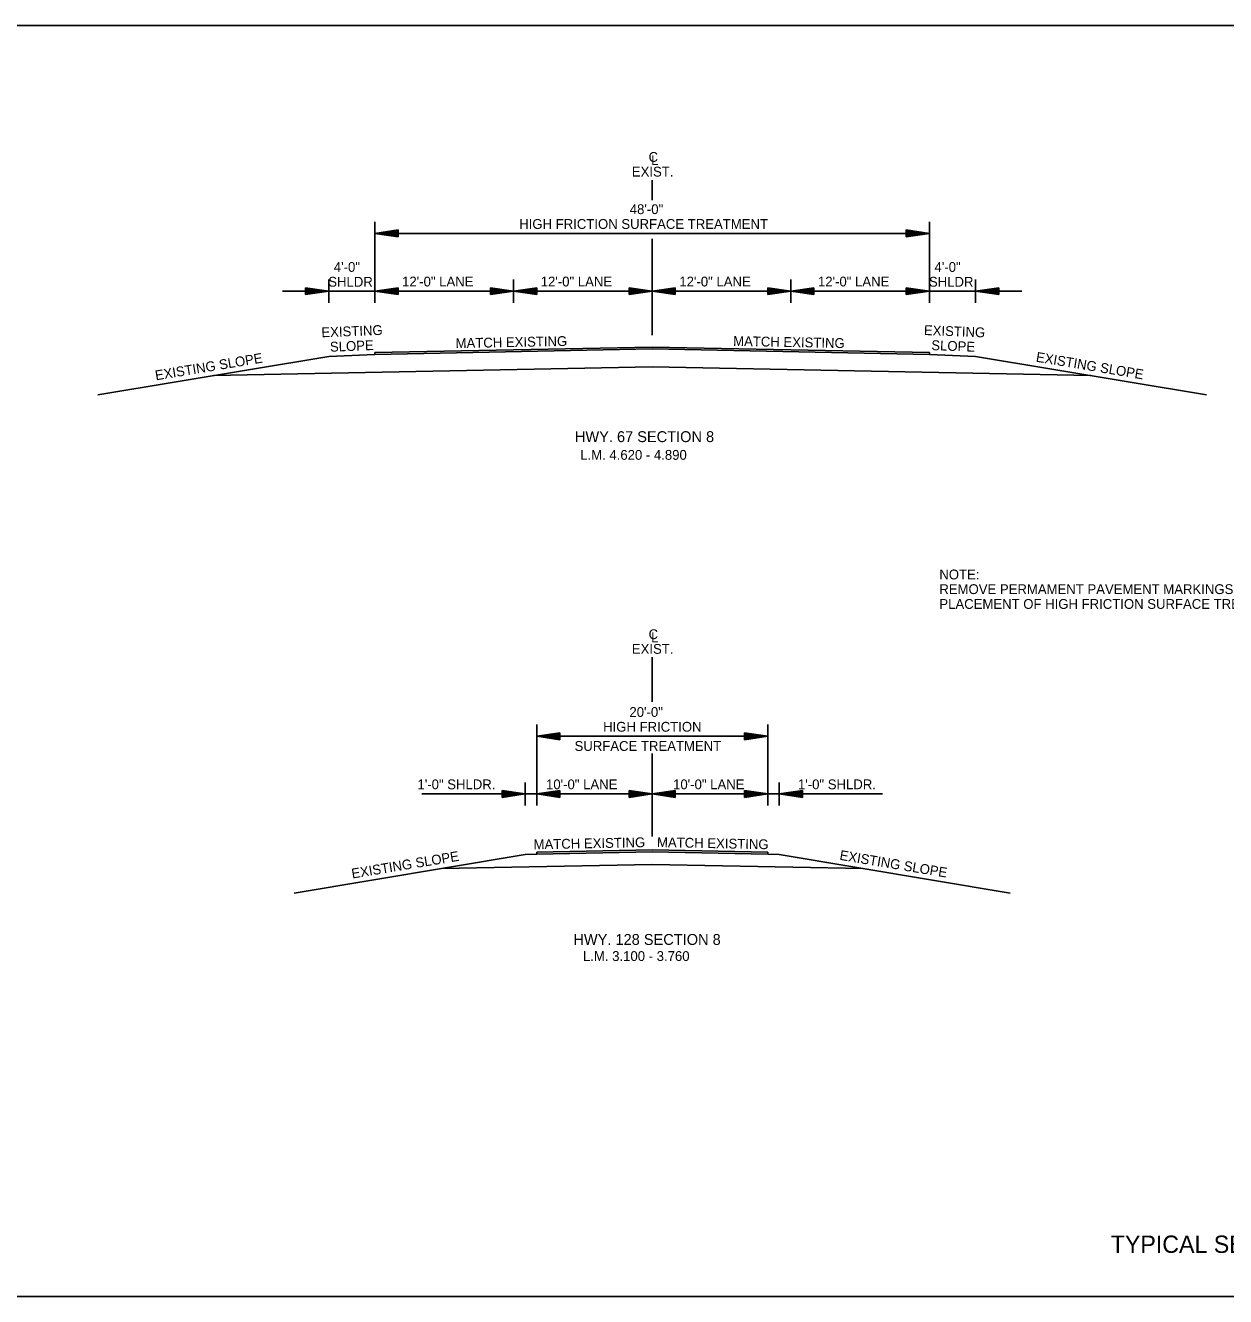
# Model space of a CAD drawing. Extents: x 96 to 721, y -177 to -41.
# Drawn here: x 376.2 to 480, y -150.6 to -40.6 of the extents above; entities that cross this region are included whole.
import ezdxf

# ---------------------------------------------------------------- set-up
doc = ezdxf.new("R2010")
doc.units = 0
for name, color, linetype in [('Default', 7, 'Continuous'), ('R_Border', 7, 'Continuous'), ('R_Draft', 7, 'Continuous'), ('SHET_Border-Lines', 7, 'Continuous'), ('SHET_Stamp-Prelim', 7, 'Continuous')]:
    doc.layers.add(name, color=color, linetype=linetype)

msp = doc.modelspace()

# ---------------------------------------------------------------- linework, layer by layer
at = {"layer": 'Default'}
for p, q in [((406.41, -69.06), (406.41, -68.89)), ((454.41, -69.06), (454.41, -68.89))]:
    msp.add_line(p, q, dxfattribs=at)
for points in [[(406.41, -68.89), (406.41, -69.06), (430.41, -68.58), (454.41, -69.06), (454.41, -68.89), (430.41, -68.41)], [(420.41, -112.13), (420.41, -112.29), (430.41, -112.09), (440.41, -112.29), (440.41, -112.13), (430.41, -111.93)]]:
    msp.add_lwpolyline(points, close=True, dxfattribs=at)
at = {"layer": 'R_Border'}
for p, q in [((430.41, -55.7), (430.41, -53.96)), ((406.41, -57.58), (406.41, -64.58)), ((454.41, -57.58), (454.41, -64.58)), ((430.41, -67.38), (430.41, -59.04)), ((402.41, -62.58), (402.41, -64.58)), ((418.41, -62.58), (418.41, -64.58)), ((430.41, -62.58), (430.41, -64.58)), ((442.41, -62.58), (442.41, -64.58)), ((458.41, -62.58), (458.41, -64.58)), ((402.41, -69.22), (382.41, -72.55)), ((406.41, -69.06), (402.41, -69.22)), ((430.41, -68.58), (406.41, -69.06)), ((430.41, -68.58), (454.41, -69.06)), ((454.41, -69.06), (458.41, -69.22)), ((458.41, -69.22), (478.41, -72.55)), ((430.41, -70.12), (392.44, -70.88)), ((430.41, -70.12), (468.37, -70.88)), ((430.41, -99.11), (430.41, -95.26)), ((420.41, -101.09), (420.41, -108.09)), ((440.41, -101.09), (440.41, -108.09)), ((430.41, -110.76), (430.41, -103.59)), ((419.41, -106.09), (419.41, -108.09)), ((430.41, -106.09), (430.41, -108.09)), ((441.41, -106.09), (441.41, -108.09)), ((430.41, -112.09), (420.41, -112.29)), ((430.41, -112.09), (440.41, -112.29)), ((419.41, -112.33), (399.41, -115.67)), ((430.41, -113.18), (412.16, -113.54)), ((420.41, -112.29), (419.41, -112.33)), ((430.41, -113.18), (448.66, -113.54)), ((440.41, -112.29), (441.41, -112.33)), ((441.41, -112.33), (461.41, -115.67))]:
    msp.add_line(p, q, dxfattribs=at)
for points in [[(345.41, -40.58), (515.41, -40.58), (515.41, -150.58), (345.41, -150.58)], [(345.41, -40.58), (345.41, -150.58), (515.41, -150.58), (515.41, -40.58)]]:
    msp.add_lwpolyline(points, close=True, dxfattribs=at)
at = {"layer": 'R_Draft'}
for p, q in [((408.41, -58.28), (406.41, -58.58)), ((408.41, -58.28), (408.41, -58.88)), ((452.41, -58.28), (454.41, -58.58)), ((452.41, -58.28), (452.41, -58.88)), ((408.41, -58.88), (406.41, -58.58)), ((406.41, -58.58), (454.41, -58.58)), ((408.41, -58.33), (406.74, -58.58)), ((408.41, -58.83), (406.74, -58.58)), ((408.41, -58.38), (407.08, -58.58)), ((408.41, -58.78), (407.08, -58.58)), ((408.41, -58.43), (407.42, -58.58)), ((408.41, -58.73), (407.42, -58.58)), ((408.41, -58.48), (407.76, -58.58)), ((408.41, -58.68), (407.76, -58.58)), ((408.41, -58.53), (408.09, -58.58)), ((408.41, -58.63), (408.09, -58.58)), ((452.41, -58.33), (454.07, -58.58)), ((452.41, -58.38), (453.73, -58.58)), ((452.41, -58.43), (453.4, -58.58)), ((452.41, -58.48), (453.06, -58.58)), ((452.41, -58.53), (452.72, -58.58)), ((452.41, -58.88), (454.41, -58.58)), ((452.41, -58.68), (453.06, -58.58)), ((452.41, -58.78), (453.73, -58.58)), ((452.41, -58.83), (454.07, -58.58)), ((452.41, -58.73), (453.4, -58.58)), ((452.41, -58.63), (452.72, -58.58)), ((402.41, -63.58), (398.41, -63.58)), ((400.41, -63.28), (402.41, -63.58)), ((400.41, -63.28), (400.41, -63.88)), ((400.41, -63.33), (402.07, -63.58)), ((400.41, -63.38), (401.73, -63.58)), ((400.41, -63.43), (401.4, -63.58)), ((400.41, -63.48), (401.06, -63.58)), ((400.41, -63.53), (400.72, -63.58)), ((400.41, -63.88), (402.41, -63.58)), ((400.41, -63.68), (401.06, -63.58)), ((400.41, -63.78), (401.73, -63.58)), ((400.41, -63.83), (402.07, -63.58)), ((400.41, -63.73), (401.4, -63.58)), ((400.41, -63.63), (400.72, -63.58)), ((406.41, -63.58), (402.41, -63.58)), ((408.41, -63.28), (406.41, -63.58)), ((406.41, -63.58), (418.41, -63.58)), ((408.41, -63.88), (406.41, -63.58)), ((408.41, -63.33), (406.74, -63.58)), ((408.41, -63.83), (406.74, -63.58)), ((408.41, -63.38), (407.08, -63.58)), ((408.41, -63.78), (407.08, -63.58)), ((408.41, -63.43), (407.42, -63.58)), ((408.41, -63.73), (407.42, -63.58)), ((408.41, -63.48), (407.76, -63.58)), ((408.41, -63.68), (407.76, -63.58)), ((408.41, -63.53), (408.09, -63.58)), ((408.41, -63.63), (408.09, -63.58)), ((408.41, -63.28), (408.41, -63.88)), ((416.41, -63.28), (418.41, -63.58)), ((416.41, -63.28), (416.41, -63.88)), ((416.41, -63.33), (418.07, -63.58)), ((416.41, -63.38), (417.73, -63.58)), ((416.41, -63.43), (417.4, -63.58)), ((416.41, -63.48), (417.06, -63.58)), ((416.41, -63.53), (416.72, -63.58)), ((416.41, -63.88), (418.41, -63.58)), ((416.41, -63.68), (417.06, -63.58)), ((416.41, -63.78), (417.73, -63.58)), ((416.41, -63.83), (418.07, -63.58)), ((416.41, -63.73), (417.4, -63.58)), ((416.41, -63.63), (416.72, -63.58)), ((420.41, -63.28), (418.41, -63.58)), ((418.41, -63.58), (430.41, -63.58)), ((420.41, -63.88), (418.41, -63.58)), ((420.41, -63.33), (418.74, -63.58)), ((420.41, -63.83), (418.74, -63.58)), ((420.41, -63.38), (419.08, -63.58)), ((420.41, -63.78), (419.08, -63.58)), ((420.41, -63.43), (419.42, -63.58)), ((420.41, -63.73), (419.42, -63.58)), ((420.41, -63.48), (419.76, -63.58)), ((420.41, -63.68), (419.76, -63.58)), ((420.41, -63.53), (420.09, -63.58)), ((420.41, -63.63), (420.09, -63.58)), ((420.41, -63.28), (420.41, -63.88)), ((428.41, -63.28), (430.41, -63.58)), ((428.41, -63.28), (428.41, -63.88)), ((428.41, -63.33), (430.07, -63.58)), ((428.41, -63.38), (429.73, -63.58)), ((428.41, -63.43), (429.4, -63.58)), ((428.41, -63.48), (429.06, -63.58)), ((428.41, -63.53), (428.72, -63.58)), ((428.41, -63.88), (430.41, -63.58)), ((428.41, -63.68), (429.06, -63.58)), ((428.41, -63.78), (429.73, -63.58)), ((428.41, -63.83), (430.07, -63.58)), ((428.41, -63.73), (429.4, -63.58)), ((428.41, -63.63), (428.72, -63.58)), ((432.41, -63.28), (430.41, -63.58)), ((430.41, -63.58), (442.41, -63.58)), ((432.41, -63.88), (430.41, -63.58)), ((432.41, -63.33), (430.74, -63.58)), ((432.41, -63.83), (430.74, -63.58)), ((432.41, -63.38), (431.08, -63.58)), ((432.41, -63.78), (431.08, -63.58)), ((432.41, -63.43), (431.42, -63.58)), ((432.41, -63.73), (431.42, -63.58)), ((432.41, -63.48), (431.76, -63.58)), ((432.41, -63.68), (431.76, -63.58)), ((432.41, -63.53), (432.09, -63.58)), ((432.41, -63.63), (432.09, -63.58)), ((432.41, -63.28), (432.41, -63.88)), ((440.41, -63.28), (442.41, -63.58)), ((440.41, -63.28), (440.41, -63.88)), ((440.41, -63.33), (442.07, -63.58)), ((440.41, -63.38), (441.73, -63.58)), ((440.41, -63.43), (441.4, -63.58)), ((440.41, -63.48), (441.06, -63.58)), ((440.41, -63.53), (440.72, -63.58)), ((440.41, -63.88), (442.41, -63.58)), ((440.41, -63.68), (441.06, -63.58)), ((440.41, -63.78), (441.73, -63.58)), ((440.41, -63.83), (442.07, -63.58)), ((440.41, -63.73), (441.4, -63.58)), ((440.41, -63.63), (440.72, -63.58)), ((444.41, -63.28), (442.41, -63.58)), ((442.41, -63.58), (454.41, -63.58)), ((444.41, -63.88), (442.41, -63.58)), ((444.41, -63.33), (442.74, -63.58)), ((444.41, -63.83), (442.74, -63.58)), ((444.41, -63.38), (443.08, -63.58)), ((444.41, -63.78), (443.08, -63.58)), ((444.41, -63.43), (443.42, -63.58)), ((444.41, -63.73), (443.42, -63.58)), ((444.41, -63.48), (443.76, -63.58)), ((444.41, -63.68), (443.76, -63.58)), ((444.41, -63.53), (444.09, -63.58)), ((444.41, -63.63), (444.09, -63.58)), ((444.41, -63.28), (444.41, -63.88)), ((452.41, -63.28), (454.41, -63.58)), ((452.41, -63.28), (452.41, -63.88)), ((452.41, -63.33), (454.07, -63.58)), ((452.41, -63.38), (453.73, -63.58)), ((452.41, -63.43), (453.4, -63.58)), ((452.41, -63.48), (453.06, -63.58)), ((452.41, -63.53), (452.72, -63.58)), ((452.41, -63.88), (454.41, -63.58)), ((452.41, -63.68), (453.06, -63.58)), ((452.41, -63.78), (453.73, -63.58)), ((452.41, -63.83), (454.07, -63.58)), ((452.41, -63.73), (453.4, -63.58)), ((452.41, -63.63), (452.72, -63.58)), ((458.41, -63.58), (454.41, -63.58)), ((460.41, -63.28), (458.41, -63.58)), ((460.41, -63.88), (458.41, -63.58)), ((462.41, -63.58), (458.41, -63.58)), ((460.41, -63.33), (458.74, -63.58)), ((460.41, -63.83), (458.74, -63.58)), ((460.41, -63.38), (459.08, -63.58)), ((460.41, -63.78), (459.08, -63.58)), ((460.41, -63.43), (459.42, -63.58)), ((460.41, -63.73), (459.42, -63.58)), ((460.41, -63.48), (459.76, -63.58)), ((460.41, -63.68), (459.76, -63.58)), ((460.41, -63.53), (460.09, -63.58)), ((460.41, -63.63), (460.09, -63.58)), ((460.41, -63.28), (460.41, -63.88)), ((422.41, -101.79), (420.41, -102.09)), ((422.41, -102.39), (420.41, -102.09)), ((420.41, -102.09), (440.41, -102.09)), ((422.41, -101.84), (420.74, -102.09)), ((422.41, -102.34), (420.74, -102.09)), ((422.41, -101.89), (421.08, -102.09)), ((422.41, -102.29), (421.08, -102.09)), ((422.41, -101.94), (421.42, -102.09)), ((422.41, -102.24), (421.42, -102.09)), ((422.41, -102), (421.76, -102.09)), ((422.41, -102.19), (421.76, -102.09)), ((422.41, -102.05), (422.09, -102.09)), ((422.41, -102.14), (422.09, -102.09)), ((422.41, -101.79), (422.41, -102.39)), ((438.41, -101.79), (440.41, -102.09)), ((438.41, -101.79), (438.41, -102.39)), ((438.41, -101.84), (440.07, -102.09)), ((438.41, -101.89), (439.73, -102.09)), ((438.41, -101.94), (439.4, -102.09)), ((438.41, -102), (439.06, -102.09)), ((438.41, -102.05), (438.72, -102.09)), ((438.41, -102.39), (440.41, -102.09)), ((438.41, -102.19), (439.06, -102.09)), ((438.41, -102.29), (439.73, -102.09)), ((438.41, -102.34), (440.07, -102.09)), ((438.41, -102.24), (439.4, -102.09)), ((438.41, -102.14), (438.72, -102.09)), ((410.47, -107.09), (419.41, -107.09)), ((417.41, -106.79), (419.41, -107.09)), ((417.41, -106.79), (417.41, -107.39)), ((417.41, -106.84), (419.07, -107.09)), ((417.41, -106.89), (418.73, -107.09)), ((417.41, -106.94), (418.4, -107.09)), ((417.41, -107), (418.06, -107.09)), ((417.41, -107.05), (417.72, -107.09)), ((417.41, -107.39), (419.41, -107.09)), ((417.41, -107.19), (418.06, -107.09)), ((417.41, -107.29), (418.73, -107.09)), ((417.41, -107.34), (419.07, -107.09)), ((417.41, -107.24), (418.4, -107.09)), ((417.41, -107.14), (417.72, -107.09)), ((420.41, -107.09), (419.41, -107.09)), ((422.41, -106.79), (420.41, -107.09)), ((420.41, -107.09), (430.41, -107.09)), ((422.41, -107.39), (420.41, -107.09)), ((422.41, -106.84), (420.74, -107.09)), ((422.41, -107.34), (420.74, -107.09)), ((422.41, -106.89), (421.08, -107.09)), ((422.41, -107.29), (421.08, -107.09)), ((422.41, -106.94), (421.42, -107.09)), ((422.41, -107.24), (421.42, -107.09)), ((422.41, -107), (421.76, -107.09)), ((422.41, -107.19), (421.76, -107.09)), ((422.41, -107.05), (422.09, -107.09)), ((422.41, -107.14), (422.09, -107.09)), ((422.41, -106.79), (422.41, -107.39)), ((428.41, -106.79), (430.41, -107.09)), ((428.41, -106.79), (428.41, -107.39)), ((428.41, -106.84), (430.07, -107.09)), ((428.41, -106.89), (429.73, -107.09)), ((428.41, -106.94), (429.4, -107.09)), ((428.41, -107), (429.06, -107.09)), ((428.41, -107.05), (428.72, -107.09)), ((428.41, -107.39), (430.41, -107.09)), ((428.41, -107.19), (429.06, -107.09)), ((428.41, -107.29), (429.73, -107.09)), ((428.41, -107.34), (430.07, -107.09)), ((428.41, -107.24), (429.4, -107.09)), ((428.41, -107.14), (428.72, -107.09)), ((432.41, -106.79), (430.41, -107.09)), ((430.41, -107.09), (440.41, -107.09)), ((432.41, -107.39), (430.41, -107.09)), ((432.41, -106.84), (430.74, -107.09)), ((432.41, -107.34), (430.74, -107.09)), ((432.41, -106.89), (431.08, -107.09)), ((432.41, -107.29), (431.08, -107.09)), ((432.41, -106.94), (431.42, -107.09)), ((432.41, -107.24), (431.42, -107.09)), ((432.41, -107), (431.76, -107.09)), ((432.41, -107.19), (431.76, -107.09)), ((432.41, -107.05), (432.09, -107.09)), ((432.41, -107.14), (432.09, -107.09)), ((432.41, -106.79), (432.41, -107.39)), ((438.41, -106.79), (440.41, -107.09)), ((438.41, -106.79), (438.41, -107.39)), ((438.41, -106.84), (440.07, -107.09)), ((438.41, -106.89), (439.73, -107.09)), ((438.41, -106.94), (439.4, -107.09)), ((438.41, -107), (439.06, -107.09)), ((438.41, -107.05), (438.72, -107.09)), ((438.41, -107.39), (440.41, -107.09)), ((438.41, -107.19), (439.06, -107.09)), ((438.41, -107.29), (439.73, -107.09)), ((438.41, -107.34), (440.07, -107.09)), ((438.41, -107.24), (439.4, -107.09)), ((438.41, -107.14), (438.72, -107.09)), ((440.41, -107.09), (441.41, -107.09)), ((443.41, -106.79), (441.41, -107.09)), ((443.41, -107.39), (441.41, -107.09)), ((441.41, -107.09), (450.35, -107.09)), ((443.41, -106.84), (441.74, -107.09)), ((443.41, -107.34), (441.74, -107.09)), ((443.41, -106.89), (442.08, -107.09)), ((443.41, -107.29), (442.08, -107.09)), ((443.41, -106.94), (442.42, -107.09)), ((443.41, -107.24), (442.42, -107.09)), ((443.41, -107), (442.76, -107.09)), ((443.41, -107.19), (442.76, -107.09)), ((443.41, -107.05), (443.09, -107.09)), ((443.41, -107.14), (443.09, -107.09)), ((443.41, -106.79), (443.41, -107.39))]:
    msp.add_line(p, q, dxfattribs=at)

# ---------------------------------------------------------------- texts
at = {"layer": 'Default'}
for s, p in [('C', (430.1, -52.39)), ('C', (430.1, -52.39)), ('L', (430.32, -52.66)), ('L', (430.32, -52.66)), ('C', (430.1, -93.69)), ('C', (430.1, -93.69)), ('L', (430.32, -93.96)), ('L', (430.32, -93.96))]:
    msp.add_text(s, height=0.85, dxfattribs=at).set_placement(p)
at = {"layer": 'SHET_Border-Lines'}
for s, height, p in [('EXIST.', 0.85, (428.65, -53.66)), ('48\'-0" ', 0.85, (428.47, -56.91)), ('HIGH FRICTION SURFACE TREATMENT', 0.85, (418.9, -58.19)), ('4\'-0"', 0.85, (402.85, -61.91)), ('4\'-0"', 0.85, (454.85, -61.91)), ('SHLDR.', 0.85, (402.37, -63.19)), ('12\'-0" LANE', 0.85, (408.76, -63.17)), ('12\'-0" LANE', 0.85, (420.76, -63.17)), ('12\'-0" LANE', 0.85, (432.76, -63.17)), ('12\'-0" LANE', 0.85, (444.76, -63.17)), ('SHLDR.', 0.85, (454.37, -63.19)), ('HWY. 67 SECTION 8', 0.943, (423.72, -76.64)), ('L.M. 4.620 - 4.890', 0.85, (424.18, -78.17)), ('NOTE:', 0.85, (455.27, -88.52)), ('REMOVE PERMAMENT PAVEMENT MARKINGS PRIOR TO THE ', 0.85, (455.27, -89.79)), ('PLACEMENT OF HIGH FRICTION SURFACE TREATMENT', 0.85, (455.27, -91.07)), ('EXIST.', 0.85, (428.65, -94.96)), ('20\'-0"', 0.85, (428.44, -100.42)), ('HIGH FRICTION', 0.85, (426.16, -101.7)), ('SURFACE TREATMENT', 0.85, (423.69, -103.36)), ('1\'-0" SHLDR.', 0.85, (410.09, -106.68)), ('10\'-0" LANE', 0.85, (421.22, -106.68)), ('10\'-0" LANE', 0.85, (432.22, -106.68)), ('1\'-0" SHLDR.', 0.85, (443.03, -106.68)), ('HWY. 128 SECTION 8', 0.943, (423.59, -120.15)), ('L.M. 3.100 - 3.760', 0.85, (424.42, -121.54))]:
    msp.add_text(s, height=height, dxfattribs=at).set_placement(p)
for s, rotation, p in [('EXISTING', 2.2906, (401.79, -67.57)), ('EXISTING', 357.7094, (453.92, -67.37)), ('SLOPE', 2.2906, (402.53, -68.82)), ('MATCH EXISTING', 1.1458, (413.4, -68.51)), ('MATCH EXISTING', 358.8542, (437.41, -68.31)), ('SLOPE', 357.7094, (454.56, -68.67)), ('EXISTING SLOPE', 9.462, (387.45, -71.3)), ('EXISTING SLOPE', 350.538, (463.59, -69.67)), ('MATCH EXISTING', 1.1458, (420.15, -111.88)), ('MATCH EXISTING', 358.8542, (430.82, -111.68)), ('EXISTING SLOPE', 9.462, (404.45, -114.41)), ('EXISTING SLOPE', 350.538, (446.59, -112.78))]:
    msp.add_text(s, height=0.85, rotation=rotation, dxfattribs=at).set_placement(p)
at = {"layer": 'SHET_Stamp-Prelim'}
msp.add_text('TYPICAL SECTIONS OF IMPROVEMENT', height=1.5, dxfattribs=at).set_placement((470.11, -146.8))

doc.saveas('drawing.dxf')
